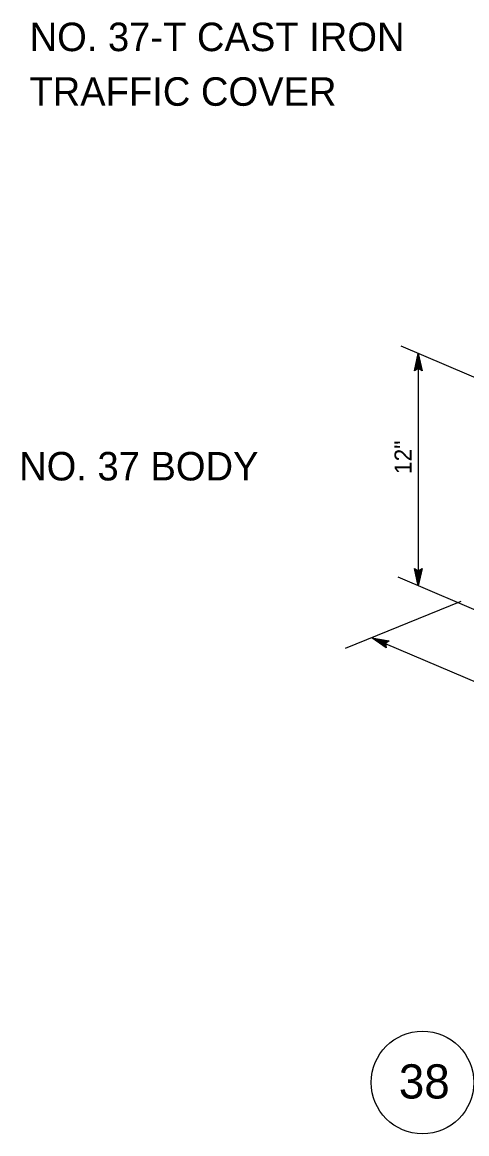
# Model space of a CAD drawing. Extents: x -123486 to -116575, y -107066 to -101122.
# Drawn here: x -117348 to -117192.1, y -101654.1 to -101264 of the extents above; entities that cross this region are included whole.
import ezdxf

# ---------------------------------------------------------------- set-up
doc = ezdxf.new("R2010")
doc.units = 0
for name, color, linetype in [('G-MARK', 7, 'Continuous'), ('G-TEXT', 7, 'Continuous'), ('Misc CnstDet(22)', 7, 'Continuous')]:
    doc.layers.add(name, color=color, linetype=linetype)

msp = doc.modelspace()

# ---------------------------------------------------------------- linework, layer by layer
at = {"layer": 'G-MARK'}
for p, q in [((-117182.3, -101391.76), (-117215.06, -101377.76)), ((-117209.07, -101380.32), (-117209.07, -101461.79)), ((-117180.54, -101473.99), (-117216.16, -101458.76)), ((-117194.18, -101467.3), (-117234.7, -101483.86)), ((-117225.38, -101480.05), (-117119.46, -101525.32))]:
    msp.add_line(p, q, dxfattribs=at)
at = {"layer": 'G-TEXT'}
for p, q in [((-117210.41, -101386.32), (-117209.07, -101380.32)), ((-117209.07, -101380.32), (-117209.07, -101380.32)), ((-117209.07, -101380.32), (-117207.74, -101386.32)), ((-117210.06, -101386.1), (-117209.07, -101381.7)), ((-117209.7, -101385.87), (-117209.08, -101383.08)), ((-117209.08, -101383.08), (-117208.45, -101385.9)), ((-117209.07, -101381.71), (-117208.1, -101386.08)), ((-117209.07, -101385.52), (-117210.41, -101386.32)), ((-117210.41, -101386.32), (-117210.41, -101386.32)), ((-117209.35, -101385.69), (-117209.08, -101384.46)), ((-117209.08, -101384.46), (-117208.81, -101385.67)), ((-117207.74, -101386.32), (-117209.07, -101385.52)), ((-117207.74, -101386.32), (-117207.74, -101386.32)), ((-117209.07, -101461.79), (-117210.4, -101455.79)), ((-117210.4, -101455.79), (-117210.4, -101455.79)), ((-117210.4, -101455.79), (-117209.07, -101456.59)), ((-117209.08, -101460.4), (-117210.04, -101456.03)), ((-117209.07, -101459.03), (-117209.7, -101456.2)), ((-117209.07, -101457.65), (-117209.34, -101456.44)), ((-117209.07, -101456.59), (-117207.73, -101455.79)), ((-117207.73, -101455.79), (-117209.07, -101461.79)), ((-117208.09, -101456.01), (-117209.07, -101460.41)), ((-117208.45, -101456.24), (-117209.07, -101459.03)), ((-117208.8, -101456.42), (-117209.07, -101457.65)), ((-117207.73, -101455.79), (-117207.73, -101455.79)), ((-117209.07, -101461.79), (-117209.07, -101461.79)), ((-117220.34, -101483.57), (-117225.38, -101480.05)), ((-117225.38, -101480.05), (-117225.38, -101480.05)), ((-117225.38, -101480.05), (-117219.32, -101481.1)), ((-117220.4, -101483.16), (-117224.1, -101480.58)), ((-117224.09, -101480.58), (-117219.68, -101481.35)), ((-117220.48, -101482.74), (-117222.82, -101481.1)), ((-117222.82, -101481.1), (-117219.97, -101481.6)), ((-117220.52, -101482.35), (-117221.55, -101481.63)), ((-117221.55, -101481.63), (-117220.33, -101481.84)), ((-117219.32, -101481.1), (-117220.57, -101482.03)), ((-117219.32, -101481.1), (-117219.32, -101481.1)), ((-117220.57, -101482.03), (-117220.34, -101483.57)), ((-117220.34, -101483.57), (-117220.34, -101483.57))]:
    msp.add_line(p, q, dxfattribs=at)
at = {"layer": 'Misc CnstDet(22)'}
msp.add_circle((-117207.59, -101636.1), 18, dxfattribs=at)

# ---------------------------------------------------------------- texts
for s, height, p in [('NO. 37-T CAST IRON', 10, (-117345.42, -101274.19)), ('TRAFFIC COVER', 10, (-117345.49, -101293.36)), ('NO. 37 BODY', 10, (-117349.11, -101424.84)), ('38', 12, (-117215.9, -101641.73))]:
    msp.add_text(s, height=height, dxfattribs=at).set_placement(p)
msp.add_text('12"', height=6, rotation=90.168, dxfattribs=at).set_placement((-117211.4, -101422.62))

doc.saveas('drawing.dxf')
